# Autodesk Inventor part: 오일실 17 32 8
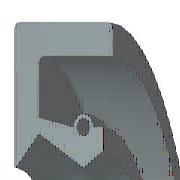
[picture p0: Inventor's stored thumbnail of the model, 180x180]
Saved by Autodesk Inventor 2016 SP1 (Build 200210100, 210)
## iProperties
IsCustomPart: 1
Created: 2012-02
Part Number: 오일실 17 32 8
Material: 고무
Description: 오일-실
Document SubType Name: Modeling
Standard: KS B 2804
Designer: mduedu
Standards Organization: KS
Language: ko-KR
Size Designation: D - 17 32 8
Categories: <MemberInstance><Categories><Category DisplayName="샤프트 부품" InternalName="7f7aeb1f-a693-4053-b835-cee3144e0d98" Mnemonic="SHFT"><Category DisplayName="실링" Intern
Density: 0.93 g/cm^3
Mass: 2.28027 g
Surface Area: 32.1224 cm^2
Volume: 2.45191 cm^3
Appearance: 고무 - 검은색 - 버전 1.1
Author: mduedu
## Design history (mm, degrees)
revolve "본체" stored, may be unused: angle "d17" = 90 deg
revolve "스프링1" stored, may be unused: angle "d18" = 90 deg
body "Solid1"
sketch "스케치1"
  geometry: L1 (0, 16)-(8, 16); L2 (8, 14.25)-(1.75, 14.25); L3 (1.75, 10.25)-(4.9, 8.5); L4 (4.9, 8.5)-(0, 8.5); L5 (0, 0)-(9.586, 0) reference; L6 (4.9, 8.5)-(6.3, 9.375); L7 (0, 18)-(0, -3) reference; L8 (-1.941, 0)-(11.507, 0) reference; L9 (4.2, 10.6)-(1.75, 11.21); L10 (1.75, 11.21)-(1.75, 14.25); L11 (0, 16)-(0, 8.588); L12 (4.9, 8.5)-(0, 8.5); L13 (1.75, 10.25)-(0.152, 8.528); L14 (8, 16)-(8, 14.25); L15 (5.6, 10.6)-(6.3, 10.6); L16 (6.3, 10.6)-(6.3, 9.375); C1 r 0.455 at (4.9, 10.6); A1 r 0.7 centre (4.9, 10.6) between (5.6, 10.6) and (4.2, 10.6); A2 r 0.088 centre (0.088, 8.588) between (0, 8.588) and (0.152, 8.528); 1 further point
  constraints: 28 end point, 5 horizontal alignment, 5 point on line, 4 point on circle, 4 vertical alignment, 3 centre point, 3 tangent, 2 collinear, 2 horizontal, 2 perpendicular, 1 coincident, 1 parallel
  dimensions: "d0" = 32 diameter of L1 L5 (= SD2); "d1" = 1.75 distance of L1.end L2.start (= SD); "d2" = 0.91 diameter of C1 (= SPDI); "d3" = 1.4 diameter of A1 (= SPDA); "d4" = 17 diameter of L3.end L5 (= NND); "d5" = 20.5 diameter of L3.start L5 (= TKDM); "d7" = 22.42 diameter of L9.end L5 (= TKDM + 0.24 x SWDT); "d8" = 1.75 distance between parallel lines of L11 L10 (= SD); "d9" = 4.9 distance from line of L11 C1.centre (= SPDST); "d10" = 21.2 diameter of C1.centre L5 (= HLDM); "d11" = 0.0875 radius of A2 (= 0.25 x LAB); "d12" = 6.3 distance between parallel lines of L11 L16 (= SDI); "d13" = 18.75 diameter of L6.end L5 (= ABDM); "d14" = 8 distance from line of L11 L1.end (= SWDT)
fillet "모깎기1" dims "d6" = 0.3 (= RR)
other parameters: "SD2" = 32 [user parameter; used in 1 equation term], "SWDT" = 8 [user parameter; used in 2 equation terms], "RR" = 0.3 [user parameter; used in 1 equation term], "SD" = 1.75 [user parameter; used in 2 equation terms], "NND" = 17 [user parameter; used in 1 equation term], "SPDA" = 1.4 [user parameter; used in 1 equation term], "SPDI" = 0.91 [user parameter; used in 1 equation term], "TKDM" = 20.5 [user parameter; used in 2 equation terms], "HLDM" = 21.2 [user parameter; used in 1 equation term], "ABDM" = 18.75 [user parameter; used in 1 equation term], "SDI" = 6.3 [user parameter; used in 1 equation term], "SPDST" = 4.9 [user parameter; used in 1 equation term], "LAB" = 0.35 [user parameter; used in 1 equation term], "d15" = 0, "d16" = 0, "d19" = 0
